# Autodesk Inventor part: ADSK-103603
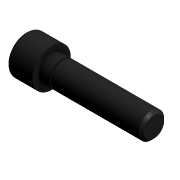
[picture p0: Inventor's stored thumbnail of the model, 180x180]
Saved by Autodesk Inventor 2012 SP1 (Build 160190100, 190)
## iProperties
Created: 2001-01
Part Number: ADSK-103603
Description: Hexagon Socket Head Cap Screw
Document SubType Name: Modeling
Standard: ANSI B18.3 - 3/8 - 16 - 1 1/2
Designer: gao
Density: 1 g/cm^3
Material: Default
Control State: 0
Master: False
Checked Out: False
Shininess: 0.0
Density: 0.0
Volumn: 0.0
Area: 0.0
PropertySet Name: Model Information
Author: gao
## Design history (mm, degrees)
node "Base1"
body "Solid1"
